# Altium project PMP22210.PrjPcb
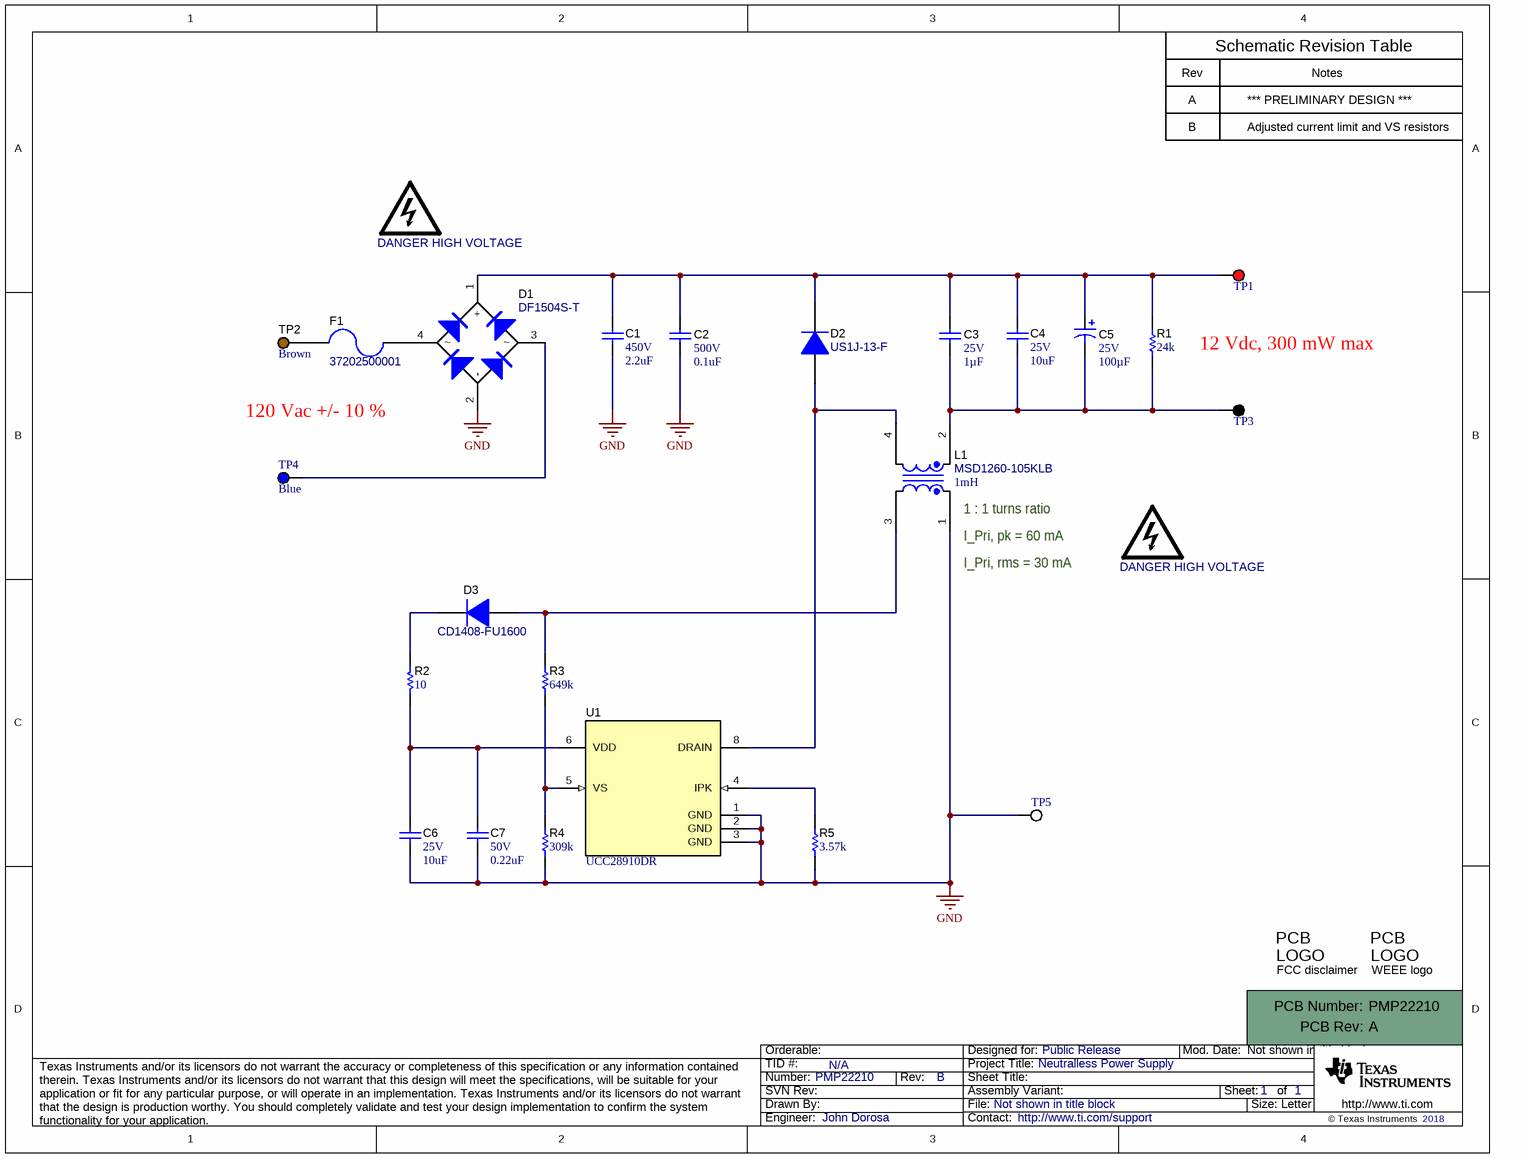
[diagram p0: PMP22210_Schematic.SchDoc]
TID: N/A; TechSupport: http://www.ti.com/support; SCH_Rev: B; PRJ_Title: Neutralless Power Supply; PRJ_Number: PMP22210; PRJ_Engineer: John Dorosa; PRJ_Customer: Public Release; PCB_Rev: A; PCB_Layout: John Dorosa; CopyrightYear: 2018
1 sheet, 28 parts. Net scope: global (net labels, ports and power ports of the same name join across sheets).
Board file: PMP22210_PCB.PcbDoc

## Sheet PMP22210_Schematic.SchDoc
size Letter; Date: Not shown in title block; ApprovedBy: Not shown in title block; CheckedBy: Not shown in title block; Author: Not shown in title block; CompanyName: Not shown in title block; Engineer: Not shown in title block; Organization: Not shown in title block; Address1: Not shown in title block; Address2: Not shown in title block; Address3: Not shown in title block; Address4: Not shown in title block; DocumentNumber: 1; Revision: Use project parameter SCH_Rev; SheetNumber: 1; SheetTotal: 1; PageSetup: Record=PageOptions¦CenterHorizontal=True¦CenterVertical=True¦PrintScale=1.00¦XCorrection=1.00¦YCorrection=1.00¦PrintKind=0¦BorderSize=5000000¦LeftOffset=0¦BottomOffset=0¦Orientation=2¦PaperLength=1000¦PaperWidth=1000¦Scale=100¦PaperSource=15¦PrintQuality=600¦MediaType=1¦DitherType=10¦PaperKind=Letter¦PrintScaleMode=1

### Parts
!PCB1  Printed Circuit Board  (value not drawn)  (mechanical)
C1  VDC_V: 450V  ValueDisplayed: 2.2uF  [2220_280]  (hidden comment: C5750X6S2W225K250KA)
C2  VDC_V: 500V  ValueDisplayed: 0.1uF  [1210_250]  (hidden comment: C1210X104KCRACTU)
C3  Cap_F: 1µF  VDC_V: 25V  [0603]  (hidden comment: GRM188R71E105KA12D)
C4  VDC_V: 25V  ValueDisplayed: 10uF  [1206_190]  (hidden comment: C1206C106K3RACTU)
C5  VDC_V: 25V  ValueDisplayed: 100µF  [UMA_800x500]  (hidden comment: UMA1E101MDD1TP)
C6  VDC_V: 25V  ValueDisplayed: 10uF  [1206_190]  (hidden comment: C1206C106K3RACTU)
C7  VDC_V: 50V  ValueDisplayed: 0.22uF  [0603]  (hidden comment: GRM188R71H224KAC4D)
D1  DF1504S-T  [DF-S]
D2  US1J-13-F  [SMA]
D3  CD1408-FU1600  [Diode_1408]
F1  37202500001  [FUSE_372]
L1  MSD1260-105KLB  value 1mH  [MSD1260]
LOGO1  DANGER HIGH VOLTAGE  [IEC_HighVoltage_Small]  (no BOM)
Logo2  FCC disclaimer  [FCC_disclaimer]  (no BOM)
Logo3  WEEE logo  [WEEE_Minimum]  (no BOM)
LOGO?  DANGER HIGH VOLTAGE  [IEC_HighVoltage_Small]  (no BOM)
R1  ValueDisplayed: 24k  [1206]  (hidden comment: CRCW120624K0JNEA)
R2  ValueDisplayed: 10  [0603]  (hidden comment: CRCW060310R0JNEA)
R3  ValueDisplayed: 649k  [0603]  (hidden comment: CRCW0603649KFKEA)
R4  ValueDisplayed: 309k  [0603]  (hidden comment: CRCW0603309KFKEA)
R5  ValueDisplayed: 3.57k  [0603]  (hidden comment: CRCW06033K57FKEA)
TP1  5010  [Keystone5010]  (value not drawn)
TP2  Color: Brown  [Keystone5125]  (hidden comment: 5125)
TP3  5011  [Keystone5011]  (value not drawn)
TP4  Color: Blue  [Keystone5127]  (hidden comment: 5127)
TP5  5012  [Keystone5012]  (value not drawn)
U1  UCC28910DR  [D0007A_N]

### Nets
GND: C1.2 C2.2 C6.2 C7.2 D1.2(-) L1.1 R4.1 R5.1 TP5.1 U1.1(GND) U1.2(GND) U1.3(GND)
NetC1_1: C1.1 C2.1 C3.1 C4.1 C5.1(+) D1.1(+) D2.1(K) R1.2 TP1.1
NetC3_2: C3.2 C4.2 C5.2(-) L1.2 R1.1 TP3.1
NetC6_1: C6.1 C7.1 R2.1 U1.6(VDD)
NetD1_3: D1.3 TP4.1
NetD1_4: D1.4 F1.1
NetD2_2: D2.2(A) L1.4 U1.8(DRAIN)
NetD3_1: D3.1(K) R2.2
NetD3_2: D3.2(A) L1.3 R3.2
NetF1_2: F1.2 TP2.1
NetR3_1: R3.1 R4.2 U1.5(VS)
NetR5_2: R5.2 U1.4(IPK)

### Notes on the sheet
- Rev
- A
- *** PRELIMINARY DESIGN ***
- Schematic Revision Table
- Notes
- B
- Adjusted current limit and VS resistors
- 12 Vdc, 300 mW max
- 120 Vac +/- 10 %
- (near L1) 1 : 1 turns ratio
- (near L1) I_Pri, pk = 60 mA
- I_Pri, rms = 30 mA

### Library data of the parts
!PCB1 = CMP-0003618-2: Manufacturer: Any; PartNumber: PMP22210
C1 = CMP-0009372-2: CAP, CERM, 2.2 uF, 450 V, +/- 10%, X6S, 2220; Manufacturer: TDK; TaMin_C: -55°C; Polarized: N; SizeAreaWB_mm2: 53.9; Value1: Unknown; U/M: EA; Value: 2.2uF; TaMax_C: 105°C; SizeZ_mm: 2.8; SizeX_mm: 5.7; SizeY_mm: 5; Cap_Case: 2220; SizeArea_mm2: 28.5; Cap_F: 2.2µF; AEC Category: Q200
C2 = CMP-0009095-1: CAP, CERM, 0.1 uF, 500 V, +/- 10%, X7R,; Manufacturer: Kemet; TaMin_C: -55°C; Polarized: N; SizeAreaWB_mm2: 14.7; Value1: Unknown; U/M: EA; Value: 0.1uF; TaMax_C: 125°C; SizeZ_mm: 2.5; SizeX_mm: 3.2; Cap_Case: 1210; SizeArea_mm2: 8; Cap_F: 100nF; AEC Category: Q200
C3 = CMP-0007405-4: CAP, CERM, 1 uF, 25 V, +/- 10%, X7R, 0603; Manufacturer: MuRata; TaMin_C: -55°C; Polarized: N; SizeAreaWB_mm2: 4.68; Value1: Unknown; U/M: EA; Value: 1uF; TaMax_C: 125°C; SizeZ_mm: 1; SizeX_mm: 1.6; SizeY_mm: 0.8; SizeArea_mm2: 1.28; AEC Category: Q200
C4 C6 = CMP-0008589-2: CAP, CERM, 10 uF, 25 V, +/- 10%, X7R, 1206_190; Manufacturer: Kemet; TaMin_C: -55°C; Polarized: N; SizeAreaWB_mm2: 10.92; Value1: Unknown; U/M: EA; Value: 10uF; TaMax_C: 125°C; SizeZ_mm: 1.9; SizeX_mm: 3.2; SizeY_mm: 1.6; Cap_Case: 1206; SizeArea_mm2: 5.12; Cap_F: 10µF; AEC Category: Q200
C5 = CMP-0084159-1: CAP, AL, 100 µF, 25 V, +/- 20%, TH; Manufacturer: Nichicon; TaMin_C: -40°C; Polarized: Y; SizeAreaWB_mm2: 100; U/M: EA; Value: 100uF; TaMax_C: 85°C; SizeZ_mm: 6; SizeX_mm: 8; Cap_Case: 8x5mm; SizeArea_mm2: 64; CompType: Capacitor; AEC Qualified: N; AEC Category: Q200
C7 = CMP-0007445-4: CAP, CERM, 0.22 uF, 50 V, +/- 10%, X7R, 0603; Manufacturer: MuRata; TaMin_C: -55°C; Polarized: N; SizeAreaWB_mm2: 4.68; Value1: Unknown; U/M: EA; Value: 0.22uF; TaMax_C: 125°C; SizeZ_mm: 1; SizeX_mm: 1.6; SizeY_mm: 0.8; SizeArea_mm2: 1.28; Cap_F: 220nF; AEC Category: Q200
D1 = CMP-0029208-3: Diode, Switching-Bridge, 400 V, 1.5 A, DF-S; Manufacturer: Diodes Inc.; SizeZ_mm: 3.4; SizeX_mm: 7.4; Green_Lifecycle: Not Set; Green_REACh: Incomplete; AEC Category: Q101; SizeArea_mm2: 62.974; SizeY_mm: 8.51; TJmax_C: 150°C; Value1: 1.5A; Value: 400V; SizeAreaWB_mm2: 98.794; Vf_V: 1.1V
D2 = CMP-0077027-2: Diode, Ultrafast, 600 V, 1 A, SMA; Manufacturer: Diodes Inc.; Value: 600V; TJmax_C: 150°C; Value1: 1A; Value2: 1.7V; SizeY_mm: 2.92; Green_REACh: Passed; Green_Lifecycle: Active; SizeX_mm: 5.59; AEC Category: Q101; SizeAreaWB_mm2: 37.3428; SizeZ_mm: 2.87; SizeArea_mm2: 16.3228
D3 = CMP-0029015-2: Diode, Ultrafast, 600 V, 1 A, 1408 Diode; Manufacturer: Bourns; RJC_CperW: 40; SizeAreaWB_mm2: 12.76; AEC Category: Q101; Green_Lifecycle: Not Set; TJmax_C: 175°C; Vf_V: 1.25V; SizeArea_mm2: 6.46; Value: 600V; Value1: 1A; AEC Qualified: N; SizeY_mm: 1.9; Green_REACh: Incomplete; SizeZ_mm: 1.15; SizeX_mm: 3.4
F1 = CMP-0003546-2: Fuse, 0.25 A, 250VAC/VDC, TH; Manufacturer: Littelfuse; Irating_A: 250mA; VAC_V: 250V
L1 = CMP-0012927-3: Coupled inductor, 1 mH, 0.34 A, 3.06 ohm, SMD; Manufacturer: Coilcraft; DCR_ohm: 3.06
LOGO1 LOGO? = CMP-0074835-1: IEC 61010-1 High Voltage Warning; SymbolCreator: a0412235
Logo2 = CMP-0074847-1: FCC_disclaimer; Library Reference: Logo
Logo3 = CMP-0074769-1
R1 = CMP-0018634-3: RES, 24 k, 5%, 0.25 W, AEC-Q200 Grade 0, 1206; Manufacturer: Vishay-Dale; Power_W: 250mW; TempCo: 200 ppm/C; Value_Code: 24k0; Value: 24k; EIA_Code: E24; SizeX_mm: 3.2; SizeY_mm: 1.6; SizeZ_mm: 1.35; Value2: 0.25W; SizeArea_mm2: 5.12; AEC Qualified: Y; VDC_V: 200V; AEC Category: Q200; AEC Grade: 0
R2 = CMP-0025703-4: RES, 10, 5%, 0.1 W, AEC-Q200 Grade 0, 0603; Manufacturer: Vishay-Dale; Power_W: 100mW; TempCo: 200 ppm/C; Value_Code: 10R0; Value: 10; EIA_Code: E24; SizeX_mm: 1.6; SizeY_mm: 0.8; SizeZ_mm: 1; Value2: 0.1W; SizeArea_mm2: 1.28; AEC Qualified: Y; VDC_V: 75V; AEC Category: Q200; AEC Grade: 0
R3 = CMP-0022542-4: RES, 649 k, 1%, 0.1 W, AEC-Q200 Grade 0, 0603; Manufacturer: Vishay-Dale; Power_W: 100mW; TempCo: 100 ppm/C; Value: 649k; EIA_Code: E96; SizeX_mm: 1.6; SizeY_mm: 0.8; SizeZ_mm: 1; Value2: 0.1W; SizeArea_mm2: 1.28; AEC Qualified: Y; VDC_V: 75V; AEC Category: Q200; AEC Grade: 0
R4 = CMP-0022322-4: RES, 309 k, 1%, 0.1 W, AEC-Q200 Grade 0, 0603; Manufacturer: Vishay-Dale; Power_W: 100mW; TempCo: 100 ppm/C; Value: 309k; EIA_Code: E96; SizeX_mm: 1.6; SizeY_mm: 0.8; SizeZ_mm: 1; Value2: 0.1W; SizeArea_mm2: 1.28; AEC Qualified: Y; VDC_V: 75V; AEC Category: Q200; AEC Grade: 0
R5 = CMP-0022378-4: RES, 3.57 k, 1%, 0.1 W, AEC-Q200 Grade 0, 0603; Manufacturer: Vishay-Dale; Power_W: 100mW; TempCo: 100 ppm/C; Value_Code: 3k57; Value: 3.57k; EIA_Code: E96; SizeX_mm: 1.6; SizeY_mm: 0.8; SizeZ_mm: 1; Value2: 0.1W; SizeArea_mm2: 1.28; AEC Qualified: Y; VDC_V: 75V; AEC Category: Q200; AEC Grade: 0
TP1 = CMP-0055147-1: Test Point, Multipurpose, Red, TH; Manufacturer: Keystone; CNHeader: FALSE; Green_Lifecycle: Active; Green_REACh: Passed; ContactFinish: Silver; CT: TRUE
TP2 = CMP-0055157-1: Test Point, Multipurpose, Brown, TH; Manufacturer: Keystone; CNHeader: FALSE; Green_Lifecycle: Active; Green_REACh: Passed; ContactFinish: Silver; CT: TRUE
TP3 = CMP-0055148-1: Test Point, Multipurpose, Black, TH; Manufacturer: Keystone; CNHeader: FALSE; Green_Lifecycle: Active; Green_REACh: Passed; ContactFinish: Silver; CT: TRUE
TP4 = CMP-0055156-1: Test Point, Multipurpose, Blue, TH; Manufacturer: Keystone; CNHeader: FALSE; Green_Lifecycle: Active; Green_REACh: Passed; ContactFinish: Silver; CT: TRUE
TP5 = CMP-0055149-1: Test Point, Multipurpose, White, TH; Manufacturer: Keystone; CNHeader: FALSE; Green_Lifecycle: Active; Green_REACh: Passed; ContactFinish: Silver; CT: TRUE
U1 = CMP-0067241-2: 700V Flyback Switcher with Constant-Voltage Constant-Current and Primary-side Control, D0007A (SOIC-7); Alternate Manufacturer: Texas Instruments; SizeAreaWB_mm2: 55.2; U/M: EA; SizeZ_mm: 1.75; SizeX_mm: 6.0; SizeY_mm: 4.9; SizeArea_mm2: 29.4; CompType: IC; AEC Category: Q200; AEC Qualified: N

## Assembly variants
001: all parts fitted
